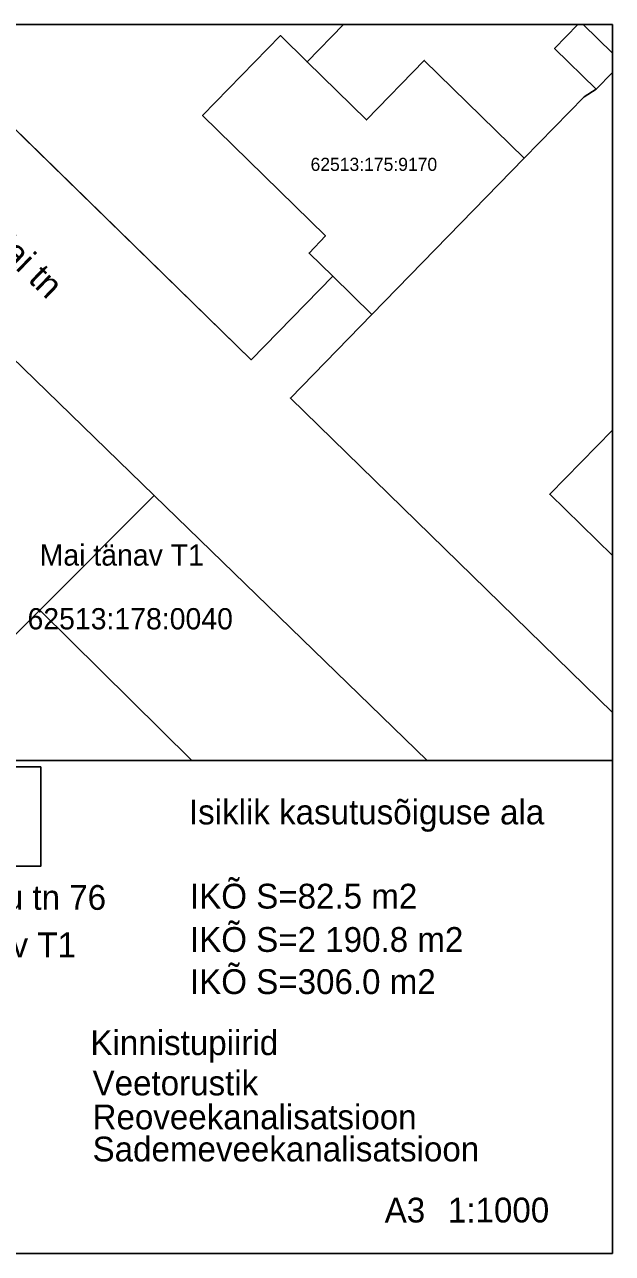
# Model space of a CAD drawing. Extents: x 531722 to 532110, y 6469397 to 6469678.
# Drawn here: x 531975.1 to 532109.7, y 6469396.9 to 6469678.3 of the extents above; entities that cross this region are included whole.
import ezdxf

# ---------------------------------------------------------------- set-up
doc = ezdxf.new("R2010")
doc.units = 0
for name, color, linetype in [('ABIJOONIS', 7, 'Continuous'), ('Default', 7, 'Continuous'), ('PIIRIMLEITUD', 7, 'Continuous'), ('VORMISTUS', 7, 'Continuous')]:
    doc.layers.add(name, color=color, linetype=linetype)

msp = doc.modelspace()

# ---------------------------------------------------------------- linework, layer by layer
at = {"layer": 'PIIRIMLEITUD'}
for points in [[(532067.33, 6469509.78), (532004.76, 6469570.47), (531966.54, 6469607.55), (531957.93, 6469615.9), (531899.65, 6469672.42), (531893.61, 6469678.27)], [(531948.34, 6469678.27), (531951.74, 6469674.95), (532027, 6469601.51), (532045.68, 6469620.66), (532054.63, 6469611.92), (532035.96, 6469592.77), (532109.74, 6469520.75)], [(532048.11, 6469678.27), (532039.78, 6469669.72), (532033.67, 6469675.75), (532015.84, 6469657.47), (532044.01, 6469629.88), (532040.26, 6469625.96), (532045.68, 6469620.66), (532027, 6469601.51), (531951.71, 6469674.94), (531954.96, 6469678.27)], [(532109.74, 6469667.33), (532106.01, 6469663.5), (532096.49, 6469672.78), (532101.84, 6469678.27)], [(532103.03, 6469678.27), (532109.74, 6469671.72)], [(532109.74, 6469520.75), (532035.96, 6469592.77), (532054.63, 6469611.92), (532089.55, 6469647.71), (532103.3, 6469661.74), (532106.01, 6469663.5), (532109.74, 6469667.33)], [(532109.74, 6469585.43), (532095.39, 6469570.72), (532109.74, 6469556.72)], [(532109.74, 6469556.72), (532095.39, 6469570.72), (532109.74, 6469585.43)], [(532013.37, 6469509.78), (531978.55, 6469544.22), (532004.76, 6469570.47), (532067.33, 6469509.78)], [(531944.16, 6469509.78), (531950.63, 6469516.26), (531978.55, 6469544.22), (532013.37, 6469509.78)]]:
    msp.add_lwpolyline(points, dxfattribs=at)
for points in [[(532045.68, 6469620.66), (532040.26, 6469625.96), (532044.01, 6469629.88), (532015.84, 6469657.47), (532033.67, 6469675.75), (532039.78, 6469669.72), (532053.38, 6469656.46), (532066.65, 6469670.05), (532089.55, 6469647.71), (532054.63, 6469611.92)], [(531966.54, 6469607.55), (532004.76, 6469570.47), (531950.63, 6469516.26), (531913.6, 6469547.88), (531908.6, 6469558.08), (531920.25, 6469564.6), (531928, 6469569.93), (531934.51, 6469575.15), (531945.28, 6469585.6)]]:
    msp.add_lwpolyline(points, close=True, dxfattribs=at)
at = {"layer": 'VORMISTUS'}
msp.add_lwpolyline([(531722.31, 6469396.91), (531927.55, 6469396.91), (531927.55, 6469509.78), (532109.74, 6469509.78), (532109.74, 6469678.27), (531722.31, 6469678.27), (531722.31, 6469396.91)], dxfattribs=at)
for points in [[(532109.74, 6469396.91), (531722.31, 6469396.91), (531722.31, 6469678.27), (532109.74, 6469678.27)], [(531936.95, 6469508.32), (531978.8, 6469508.32), (531978.8, 6469485.56), (531936.95, 6469485.56)]]:
    msp.add_lwpolyline(points, close=True, dxfattribs=at)

# ---------------------------------------------------------------- texts
at = {"layer": 'ABIJOONIS'}
msp.add_text('62513:175:9170', height=3, dxfattribs=at).set_placement((532040.59, 6469644.77))
msp.add_text('Mai tn', height=5.851, rotation=316.0369, dxfattribs=at).set_placement((531965, 6469629.93))
at = {"layer": 'Default'}
for s, p in [('Mai tänav T1', (531978.54, 6469554.39)), ('62513:178:0040', (531975.75, 6469539.79))]:
    msp.add_text(s, height=4.8664, dxfattribs=at).set_placement(p)
for s, height, rotation, p in [('Isiklik kasutusõiguse ala', 5.6737, 360, (532012.73, 6469495.14)), ('IKÕ S=82.5 m2', 5.6737, 360, (532012.96, 6469475.87)), ('Papiniidu tn 76', 5.6737, 360, (531943.55, 6469475.58)), ('IKÕ S=2 190.8 m2', 5.6737, 360, (532012.96, 6469465.95)), ('Mai tänav T1', 5.6737, 360, (531943.01, 6469464.73)), ('IKÕ S=306.0 m2', 5.6737, 360, (532012.96, 6469456.3)), ('Kinnistupiirid', 5.6737, 360, (531990.16, 6469442.32)), ('Veetorustik', 5.6737, 360, (531990.65, 6469433.1)), ('Reoveekanalisatsioon', 5.6737, 360, (531990.65, 6469425.32)), ('Sademeveekanalisatsioon', 5.6737, 360, (531990.65, 6469417.97)), ('A3', 5.674, 0.0792, (532057.57, 6469403.98)), ('1:1000', 5.674, 0.0792, (532072.06, 6469403.98))]:
    msp.add_text(s, height=height, rotation=rotation, dxfattribs=at).set_placement(p)

doc.saveas('drawing.dxf')
